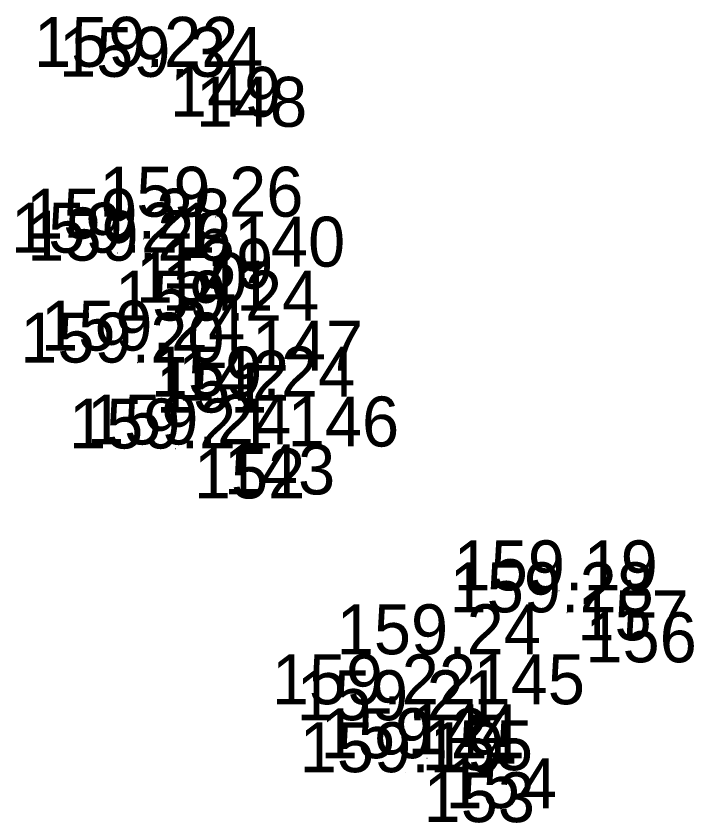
# Model space of a CAD drawing. Extents: x -583198 to -582878, y -1211024 to -1210637.
# Drawn here: x -583198.097 to -583194.704, y -1210978.824 to -1210974.786 of the extents above; entities that cross this region are included whole.
import ezdxf

# ---------------------------------------------------------------- set-up
doc = ezdxf.new("R2010")
doc.units = 0
for name, color, linetype in [('4   Body podrobné', 7, 'Continuous'), ('5   Body podrobné - čísla', 7, 'Continuous'), ('6   Body podrobné - výšky', 7, 'Continuous')]:
    doc.layers.add(name, color=color, linetype=linetype)

msp = doc.modelspace()

# ---------------------------------------------------------------- linework, layer by layer
at = {"layer": '4   Body podrobné'}
for p, q in [((-583197.42, -1210975.04), (-583197.419, -1210975.04)), ((-583197.29, -1210975.09), (-583197.289, -1210975.09)), ((-583197.1, -1210975.79), (-583197.099, -1210975.79)), ((-583197.46, -1210975.9), (-583197.459, -1210975.9)), ((-583197.59, -1210975.97), (-583197.589, -1210975.97)), ((-583197.46, -1210976.01), (-583197.459, -1210976.01)), ((-583197.01, -1210976.31), (-583197.009, -1210976.31)), ((-583197.38, -1210976.46), (-583197.379, -1210976.46)), ((-583197.49, -1210976.52), (-583197.489, -1210976.52)), ((-583196.83, -1210976.69), (-583196.829, -1210976.69)), ((-583197.15, -1210976.93), (-583197.149, -1210976.93)), ((-583197.3, -1210976.95), (-583197.299, -1210976.95)), ((-583195.38, -1210977.66), (-583195.379, -1210977.66)), ((-583195.34, -1210977.77), (-583195.339, -1210977.77)), ((-583195.9, -1210977.98), (-583195.899, -1210977.98)), ((-583196.23, -1210978.23), (-583196.229, -1210978.23)), ((-583196.16, -1210978.31), (-583196.159, -1210978.31)), ((-583196.04, -1210978.5), (-583196.039, -1210978.5)), ((-583196.15, -1210978.57), (-583196.149, -1210978.57))]:
    msp.add_line(p, q, dxfattribs=at)

# ---------------------------------------------------------------- texts
at = {"layer": '5   Body podrobné - čísla'}
for s, p in [(' 149', (-583197.42, -1210975.29)), (' 148', (-583197.29, -1210975.34)), (' 140', (-583197.1, -1210976.04)), (' 139', (-583197.46, -1210976.15)), (' 150', (-583197.59, -1210976.22)), (' 141', (-583197.46, -1210976.26)), (' 147', (-583197.01, -1210976.56)), (' 142', (-583197.38, -1210976.71)), (' 151', (-583197.49, -1210976.77)), (' 146', (-583196.83, -1210976.94)), (' 143', (-583197.15, -1210977.18)), (' 152', (-583197.3, -1210977.2)), (' 157', (-583195.38, -1210977.91)), (' 156', (-583195.34, -1210978.02)), (' 145', (-583195.9, -1210978.23)), (' 144', (-583196.23, -1210978.48)), (' 155', (-583196.16, -1210978.56)), (' 154', (-583196.04, -1210978.75)), (' 153', (-583196.15, -1210978.82))]:
    msp.add_text(s, height=0.25, dxfattribs=at).set_placement(p)
at = {"layer": '6   Body podrobné - výšky'}
for s, p in [('159.22', (-583198.007, -1210975.04)), ('159.34', (-583197.882, -1210975.09)), ('159.26', (-583197.681, -1210975.79)), ('159.28', (-583198.047, -1210975.9)), ('159.21', (-583198.122, -1210975.97)), ('159.26', (-583198.041, -1210976.01)), ('159.24', (-583197.602, -1210976.31)), ('159.24', (-583197.972, -1210976.46)), ('159.20', (-583198.076, -1210976.52)), ('159.24', (-583197.422, -1210976.69)), ('159.21', (-583197.832, -1210976.95)), ('159.24', (-583197.742, -1210976.93)), ('159.19', (-583195.907, -1210977.66)), ('159.28', (-583195.927, -1210977.77)), ('159.24', (-583196.492, -1210977.98)), ('159.22', (-583196.817, -1210978.23)), ('159.21', (-583196.692, -1210978.31)), ('159.21', (-583196.572, -1210978.5)), ('159.19', (-583196.677, -1210978.57))]:
    msp.add_text(s, height=0.25, dxfattribs=at).set_placement(p)

doc.saveas('drawing.dxf')
